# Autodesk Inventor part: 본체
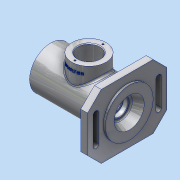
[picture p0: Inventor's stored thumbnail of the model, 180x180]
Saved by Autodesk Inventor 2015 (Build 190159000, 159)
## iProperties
Created: 2017-10
Part Number: 본체
Material: 알루미늄 6061
Document SubType Name: Modeling
Designer: SCD-A13
Density: 2.7 g/cm^3
Appearance: 알루미늄 - 평지
Mass: 730.425 g
Surface Area: 657.614 cm^2
Volume: 270.528 cm^3
Author: SCD-A13
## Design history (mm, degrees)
sketch "스케치1"
  geometry: L1 (-57.5, 0)-(57.5, 0); L2 (-57.5, 31)-(57.5, 31); L3 (57.5, 31)-(57.5, 0); L4 (57.5, 0)-(-57.5, 0); L5 (-57.5, 0)-(-57.5, 31); 2 further points
  constraints: 10 end point, 2 horizontal, 2 midpoint, 2 parallel, 1 coincident, 1 perpendicular
  dimensions: "d0" = 115 distance of L1.start L1.end; "d1" = 62 diameter of L2 L1; "d2" = 115 distance between parallel lines of L3 L5
revolve "회전1" sketch "스케치1" stored, may be unused: angle "d3" = 90 deg
node "작업 평면1"
sketch "스케치3"
  geometry: L1 (-38, -47)-(38, -47); L2 (58, -27)-(58, 27); L3 (38, 47)-(-38, 47); L4 (-58, 27)-(-58, -27); L5 (-58, -47)-(58, 47); L6 (58, -47)-(-58, 47); L7 (-38, 47)-(-58, 27); L8 (-58, -27)-(-38, -47); L9 (38, -47)-(58, -27); L10 (58, 27)-(38, 47); C1 r 31 at (0, 0) reference; 1 further point
  constraints: 20 end point, 8 point on line, 2 midpoint, 2 parallel, 1 horizontal, 1 perpendicular
  dimensions: "d15" = 116 distance of L6.end L5.end; "d16" = 94 distance of L5.end L6.start; "d17" = 20 distance of L3.end L6.end; "d18" = 20 distance of L4.start L6.end (= d17); "d19" = 20 distance of L4.end L5.start (= d17); "d20" = 20 distance of L1.start L5.start (= d19); "d21" = 20 distance of L1.end L6.start (= d17); "d22" = 20 distance of L2.start L6.start (= d21); "d23" = 20 distance of L2.end L5.end (= d17); "d24" = 20 distance of L3.start L5.end (= d23)
extrude "돌출1" join sketch "스케치3" distance "d25" = 10; taper "d26" = 0 deg
sketch "스케치4"
  geometry: 1 further point
revolve "회전2" stored, may be unused: angle "d61" = 90 deg
sketch "스케치6"
  geometry: L1 (38, 47)-(-38, 47) reference; L2 (-46, 20)-(-46, -20); L3 (-50, 20)-(-50, -20); L4 (-42, -20)-(-42, 20); L5 (0, 0)-(0, 47); L6 (42, -20)-(42, 20); L7 (50, 20)-(50, -20); C1 r 31 at (0, 0) reference; A1 r 4 centre (-46, 20) between (-42, 20) and (-50, 20); A2 r 4 centre (-46, -20) between (-50, -20) and (-42, -20); A3 r 4 centre (46, 20) between (50, 20) and (42, 20); A4 r 4 centre (46, -20) between (42, -20) and (50, -20); 1 further point
  constraints: 14 end point, 8 point on circle, 6 symmetric about line, 4 centre point, 4 tangent, 2 midpoint, 1 horizontal alignment, 1 parallel, 1 vertical, 2 other
  dimensions: "d62" = 40 distance of L2.start L2.end; "d63" = 8 diameter of A2; "d64" = 92 distance of A4.centre L2.end
extrude "돌출2" cut sketch "스케치6" stored distance "d65" = 10; taper "d66" = 0 deg
sketch "스케치7"
  geometry: L1 (-112, 7)-(-112, 69) reference; C1 r 16 at (-56, 38); C2 r 25 at (-56, 38); 1 further point
  constraints: 2 centre point, 1 coincident
  dimensions: "d67" = 32 diameter of C1; "d68" = 50 diameter of C2; "d69" = 56 distance from line of L1 C1.centre
extrude "돌출3" join sketch "스케치7" stored distance "d70" = 10; taper "d71" = 0 deg
extrude "돌출4" cut sketch "스케치7" stored distance "d72" = 10; taper "d73" = 0 deg
sketch "스케치8" dims "d74" = 41
  geometry: C1 r 25 at (0, 0) reference; 3 further points
  constraints: 1 coincident, 1 vertical alignment, 2 other
hole "구멍1" sketch "스케치8" at (0, 20.5) diameter "d75" = 2.459; stored, may be unused: countersink angle "d79" = 90 deg, drill point angle "d81" = 118 deg; dims "d76" = 6, "d77" = 4, "d78" = 2, "d80" = 8
sketch "스케치9"
  geometry: L1 (-112, -4)-(-112, 58) reference; L2 (-81, 74)-(-31, 74) reference; 2 further points
  constraints: 1 other
  dimensions: "d85" = 56 distance from line of point (-56, 64) L1; "d86" = 10 distance from line of L2 point (-56, 64)
feature "엠보싱1" sketch "스케치9" dims "d20" = 20 (= d19), "d87" = 0.5, "d88" = 0
fillet "모깎기1" dims "d89" = 0.3
chamfer "모따기1" distance "d90" = 0.7; stored, may be unused: second distance "d91" = 2, angle "d92" = 45 deg
fillet "모깎기2" dims "d93" = 3
fillet "모깎기3" dims "d94" = 0.3
sketch "스케치10"
  geometry: C1 r 31 at (0, 0) reference; 1 further point
  constraints: 1 coincident
hole "구멍2" sketch "스케치10" at (0, 0) diameter "d95" = 40.376; stored, may be unused: countersink angle "d99" = 90 deg, drill point angle "d101" = 118 deg; dims "d96" = 9, "d97" = 4, "d98" = 2, "d100" = 12
fillet "모깎기4" dims "d102" = 3
chamfer "모따기2" distance "d103" = 1; stored, may be unused: second distance "d104" = 2, angle "d105" = 45 deg
sketch "스케치11"
  geometry: C1 r 31 at (0, 0) reference; C2 r 35 at (0, 0)
  constraints: 1 centre point, 1 coincident
  dimensions: "d107" = 35 radius of C2
extrude "돌출5" join sketch "스케치11" distance "d108" = 3; taper "d109" = 0 deg
node "솔리드1"
pattern_circular "원형 패턴1" dims angle "d83" = 360 deg
sketch "스케치5"
  geometry: L1 (-48.5, 0)-(-48.5, 24); L2 (-48.5, 24)-(-45.5, 24); L3 (-45.5, 24)-(-45.5, 20); L4 (-45.5, 20)-(-36.5, 20); L5 (-36.5, 20)-(-36.5, 17.5); L6 (-36.5, 17.5)-(-33.25, 17.5); L7 (-33.25, 17.5)-(-33.25, 18.5); L8 (-33.25, 18.5)-(-31.5, 18.5); L9 (-31.5, 18.5)-(-31.5, 17.5); L10 (-31.5, 17.5)-(-20.5, 17.5); L11 (-20.5, 17.5)-(-20.5, 26); L12 (-20.5, 26)-(17.5, 26); L13 (17.5, 26)-(17.5, 17.5); L14 (17.5, 17.5)-(28.5, 17.5); L15 (28.5, 17.5)-(28.5, 16.5); L16 (43.5, 16)-(57.5, 22); L17 (57.5, -31)-(57.5, 31) reference; L18 (-57.5, -31)-(-57.5, 31) reference; L19 (57.5, 0)-(57.5, 22); L20 (-57.5, 0)-(57.5, 0); L21 (28.5, 16.5)-(33.5, 16.5); L22 (33.5, 16.5)-(33.5, 10); L23 (33.5, 10)-(36.2, 10); L24 (36.2, 10)-(36.2, 12.5); L25 (36.2, 12.5)-(43.5, 12.5); L26 (43.5, 12.5)-(43.5, 16); 2 further points
  constraints: 48 end point, 20 perpendicular, 5 point on line, 2 midpoint, 1 collinear, 1 horizontal
  dimensions: "d27" = 14 horizontal distance of L16.start L16.end; "d33" = 3 distance of L1.end L2.end; "d34" = 12 distance from line of L3 point (-57.5, 21); "d36" = 21 distance between parallel lines of L5 L18; "d37" = 26 distance from line of L8.end L18; "d38" = 1.75 distance of L7.end L8.end; "d41" = 38 distance of L11.end L12.end; "d42" = 60 horizontal distance of L14.end L8.end; "d43" = 11 distance of L9.end L10.end; "d45" = 52 diameter of L12 L20; "d46" = 35 diameter of L10 L20; "d47" = 37 diameter of L7.end L20; "d48" = 40 diameter of L4 L20; "d50" = 48 diameter of L2 L20; "d51" = 35 diameter of L14 L20; "d52" = 5 distance of L15.end L21.end; "d53" = 33 diameter of L21 L20; "d54" = 32 diameter of L16.start L20; "d55" = 25 diameter of L25 L20; "d56" = 20 diameter of L23 L20; "d57" = 44 diameter of L16.end L20; "d59" = 2.7 distance of L22.end L23.end; "d60" = 115 distance of L20.start L19.start (derived)
node "절단 모서리 투영1"
other parameters: "d14" = -3
